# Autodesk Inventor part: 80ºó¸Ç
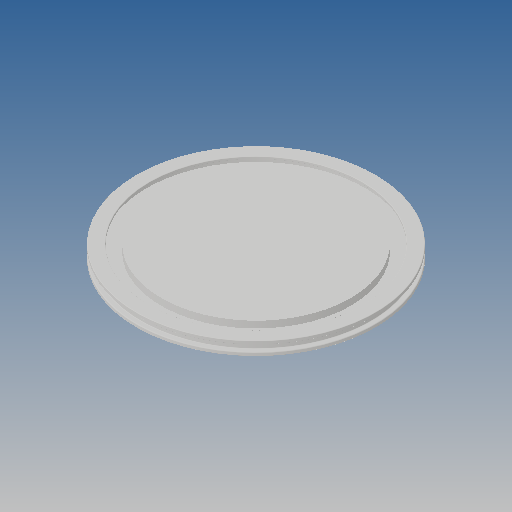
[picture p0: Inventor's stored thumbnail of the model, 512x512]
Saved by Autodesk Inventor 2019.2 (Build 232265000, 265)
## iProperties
Created: 2013-07
Part Number: 80ºó¸Ç
Material: Ogólny
Document SubType Name: Modeling
Designer: CADENGINEERING4
Density: 1 g/cm^3
Appearance: Domyślna
Author: CADENGINEERING4
Revision Number: ÈÎºÎ
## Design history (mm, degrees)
feature "Ðý×ª1"
node "Bryła1"
